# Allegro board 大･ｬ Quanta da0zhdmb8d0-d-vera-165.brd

Outline 236.75 x 98.9 mm; copper layers: TOP, SGND, IN1, SGND1, SVCC, IN2, SGND2, BOTTOM. Coordinates in mm from the lower left corner of the outline.

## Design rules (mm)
net group EDP_TX_DN*: nets EDP_TX_DN*<0> EDP_TX_DN*<1>
net group EDP_TX_DP: nets EDP_TX_DP<0> EDP_TX_DP<1>
net group M_A_CLK_DDR_DN*: nets M_A_CLK_DDR_DN*<0> M_A_CLK_DDR_DN*<1>
net group M_A_CLK_DDR_DP: nets M_A_CLK_DDR_DP<0> M_A_CLK_DDR_DP<1>
net group M_A_CS*: nets M_A_CS*<0> M_A_CS*<1>
net group M_B_CLK_DDR_DN*: nets M_B_CLK_DDR_DN*<0> M_B_CLK_DDR_DN*<1>
net group M_B_CLK_DDR_DP: nets M_B_CLK_DDR_DP<0> M_B_CLK_DDR_DP<1>
net group M_B_CS*: nets M_B_CS*<0> M_B_CS*<1>
net group TP_M_A_A: nets TP_M_A_A<3> TP_M_A_A<4>
net group TP_M_B_A: nets TP_M_B_A<3> TP_M_B_A<4>
net group USBC1_R_SSRXN*: nets USBC1_R_SSRXN*<1> USBC1_R_SSRXN*<2>
net group USBC1_R_SSRXP: nets USBC1_R_SSRXP<1> USBC1_R_SSRXP<2>
net group USBC1_SSRXP: nets USBC1_SSRXP<1> USBC1_SSRXP<2>
net group USBC1_SSTXN*: nets USBC1_SSTXN*<1> USBC1_SSTXN*<2>
net group USBC1_SSTXP: nets USBC1_SSTXP<1> USBC1_SSTXP<2>
net group W12-T12B: nets USB_C0_CC1_CONN USB_C0_CC2_CONN
net group W40-T12B: nets HP_RING2 MIC_P
net group XDP_BPM: nets XDP_BPM<2> XDP_BPM<3>
net group CFG: nets CFG<0> CFG<2> CFG<3> CFG<4> CFG<5> CFG<6> CFG<8> CFG<9> CFG<10>
net group DDI1_LANE_DN*: nets DDI1_LANE_DN*<0> DDI1_LANE_DN*<1> DDI1_LANE_DN*<2> DDI1_LANE_DN*<3>
net group DDI1_LANE_DP: nets DDI1_LANE_DP<0> DDI1_LANE_DP<1> DDI1_LANE_DP<2> DDI1_LANE_DP<3>
net group DDI2_LANE_DN*: nets DDI2_LANE_DN*<0> DDI2_LANE_DN*<1> DDI2_LANE_DN*<2> DDI2_LANE_DN*<3>
net group DDI2_LANE_DP: nets DDI2_LANE_DP<0> DDI2_LANE_DP<1> DDI2_LANE_DP<2> DDI2_LANE_DP<3>
net group DFP-S4.3(4.2)W4.01(3.11)-T12B: nets DDI1_AUX_DN* DDI1_AUX_DP DDI1_C_AUX_DN DDI1_C_AUX_DP DDI2_CTRL_CLK DDI2_CTRL_DATA EDP_AUX_DN* EDP_AUX_DP EDP_AUXN_C_DN EDP_AUXP_C_DP EDP_TXN0_C_DN EDP_TXN1_C_DN EDP_TXP0_C_DP EDP_TXP1_C_DP HDMI_DDCCLK_MB HDMI_DDCDATA_MB INT_HDMICLK+_IC INT_HDMICLK-_IC INT_HDMITX0N_IC INT_HDMITX0P_IC INT_HDMITX1N_IC INT_HDMITX1P_IC INT_HDMITX2N_IC INT_HDMITX2P_IC USB1_BC_DN USB1_BC_DP USB2_1_DN* USB2_1_DP USB2_A_DN* USB2_A_DN_CONN* USB2_A_DP USB2_A_DP_CONN USB3_A_TX_DN* USB3_A_TX_DP USBC1_DN* USBC1_DP USBC1_SSUSBC1_AUX_RFU1 USBC1_SSUSBC1_AUX_RFU1_C USBC1_SSUSBC1_AUX_RFU2 USBC1_SSUSBC1_AUX_RFU2_C WIFI_PCIE_CLK_DN WIFI_PCIE_CLK_DP
net group DFP-S10(9)W4(3)-T12B: nets INT_HDMICLK+_LS INT_HDMICLK-_LS INT_HDMITX0N_LS INT_HDMITX0P_LS INT_HDMITX1N_LS INT_HDMITX1P_LS INT_HDMITX2N_LS INT_HDMITX2P_LS
net group DFP-S10(9)W4.01(3.11)-T12B: nets INT_HDMICLK+_C INT_HDMICLK-_C INT_HDMITX0N_C INT_HDMITX0P_C INT_HDMITX1N_C INT_HDMITX1P_C INT_HDMITX2N_C INT_HDMITX2P_C
net group DFP-S10W4(3)-T1B: nets I2C4_SCL I2C4_SCL_C I2C4_SDA I2C4_SDA_C
net group DFP-S10W4(3.1)-T12B: nets EC_MUX_CLK EC_MUX_SDA EC_PD_I2C_CLK EC_PD_I2C_SDA EC_ROP_I2C_CLK EC_ROP_I2C_SDA EC_SMB_CLK EC_SMB_SDA I2C1_SCL I2C1_SDA I2C_SCL_INA I2C_SDA_INA
net group DFP-S10W12-T12B: nets VCCCORE_SENSE VCCGT_SENSE VCCSA_SENSE VSSCORE_SENSE VSSGT_SENSE VSSSA_SENSE
net group EMMC_D: nets EMMC_D<0> EMMC_D<1> EMMC_D<2> EMMC_D<3> EMMC_D<4> EMMC_D<5> EMMC_D<6> EMMC_D<7>
net group LPC_LAD: nets LPC_LAD<0> LPC_LAD<1> LPC_LAD<2> LPC_LAD<3>
net group M_A_CA_A: nets M_A_CA_A<0> M_A_CA_A<1> M_A_CA_A<2> M_A_CA_A<3> M_A_CA_A<4> M_A_CA_A<5> M_A_CA_A<6> M_A_CA_A<7> M_A_CA_A<8> M_A_CA_A<9>
net group M_A_CA_B: nets M_A_CA_B<0> M_A_CA_B<1> M_A_CA_B<2> M_A_CA_B<3> M_A_CA_B<4> M_A_CA_B<5> M_A_CA_B<6> M_A_CA_B<7> M_A_CA_B<8> M_A_CA_B<9>
net group M_A_CKE: nets M_A_CKE<0> M_A_CKE<1> M_A_CKE<2> M_A_CKE<3>
net group M_A_DQ: nets M_A_DQ<0> M_A_DQ<1> M_A_DQ<2> M_A_DQ<3> M_A_DQ<4> M_A_DQ<5> M_A_DQ<6> M_A_DQ<7> M_A_DQ<8> M_A_DQ<9> M_A_DQ<10> M_A_DQ<11> M_A_DQ<12> M_A_DQ<13> M_A_DQ<14> M_A_DQ<15> M_A_DQ<16> M_A_DQ<17> M_A_DQ<18> M_A_DQ<19> M_A_DQ<20> M_A_DQ<21> M_A_DQ<22> M_A_DQ<23> M_A_DQ<24> M_A_DQ<25> M_A_DQ<26> M_A_DQ<27> M_A_DQ<28> M_A_DQ<29> M_A_DQ<30> M_A_DQ<31> M_A_DQ<32> M_A_DQ<33> M_A_DQ<34> M_A_DQ<35> M_A_DQ<36> M_A_DQ<37> M_A_DQ<38> M_A_DQ<39> M_A_DQ<40> M_A_DQ<41> M_A_DQ<42> M_A_DQ<43> M_A_DQ<44> M_A_DQ<45> M_A_DQ<46> M_A_DQ<47> M_A_DQ<48> M_A_DQ<49> M_A_DQ<50> M_A_DQ<51> M_A_DQ<52> M_A_DQ<53> M_A_DQ<54> M_A_DQ<55> M_A_DQ<56> M_A_DQ<57> M_A_DQ<58> M_A_DQ<59> M_A_DQ<60> M_A_DQ<61> M_A_DQ<62> M_A_DQ<63>
net group M_A_DQS_DN*: nets M_A_DQS_DN*<0> M_A_DQS_DN*<1> M_A_DQS_DN*<2> M_A_DQS_DN*<3> M_A_DQS_DN*<4> M_A_DQS_DN*<5> M_A_DQS_DN*<6> M_A_DQS_DN*<7>
net group M_A_DQS_DP: nets M_A_DQS_DP<0> M_A_DQS_DP<1> M_A_DQS_DP<2> M_A_DQS_DP<3> M_A_DQS_DP<4> M_A_DQS_DP<5> M_A_DQS_DP<6> M_A_DQS_DP<7>
net group M_A_ODT: nets M_A_ODT<0>
net group M_B_CA_A: nets M_B_CA_A<0> M_B_CA_A<1> M_B_CA_A<2> M_B_CA_A<3> M_B_CA_A<4> M_B_CA_A<5> M_B_CA_A<6> M_B_CA_A<7> M_B_CA_A<8> M_B_CA_A<9>
net group M_B_CA_B: nets M_B_CA_B<0> M_B_CA_B<1> M_B_CA_B<2> M_B_CA_B<3> M_B_CA_B<4> M_B_CA_B<5> M_B_CA_B<6> M_B_CA_B<7> M_B_CA_B<8> M_B_CA_B<9>
net group M_B_CKE: nets M_B_CKE<0> M_B_CKE<1> M_B_CKE<2> M_B_CKE<3>
net group M_B_DQ: nets M_B_DQ<0> M_B_DQ<1> M_B_DQ<2> M_B_DQ<3> M_B_DQ<4> M_B_DQ<5> M_B_DQ<6> M_B_DQ<7> M_B_DQ<8> M_B_DQ<9> M_B_DQ<10> M_B_DQ<11> M_B_DQ<12> M_B_DQ<13> M_B_DQ<14> M_B_DQ<15> M_B_DQ<16> M_B_DQ<17> M_B_DQ<18> M_B_DQ<19> M_B_DQ<20> M_B_DQ<21> M_B_DQ<22> M_B_DQ<23> M_B_DQ<24> M_B_DQ<25> M_B_DQ<26> M_B_DQ<27> M_B_DQ<28> M_B_DQ<29> M_B_DQ<30> M_B_DQ<31> M_B_DQ<32> M_B_DQ<33> M_B_DQ<34> M_B_DQ<35> M_B_DQ<36> M_B_DQ<37> M_B_DQ<38> M_B_DQ<39> M_B_DQ<40> M_B_DQ<41> M_B_DQ<42> M_B_DQ<43> M_B_DQ<44> M_B_DQ<45> M_B_DQ<46> M_B_DQ<47> M_B_DQ<48> M_B_DQ<49> M_B_DQ<50> M_B_DQ<51> M_B_DQ<52> M_B_DQ<53> M_B_DQ<54> M_B_DQ<55> M_B_DQ<56> M_B_DQ<57> M_B_DQ<58> M_B_DQ<59> M_B_DQ<60> M_B_DQ<61> M_B_DQ<62> M_B_DQ<63>
net group M_B_DQS_DN*: nets M_B_DQS_DN*<0> M_B_DQS_DN*<1> M_B_DQS_DN*<2> M_B_DQS_DN*<3> M_B_DQS_DN*<4> M_B_DQS_DN*<5> M_B_DQS_DN*<6> M_B_DQS_DN*<7>
net group M_B_DQS_DP: nets M_B_DQS_DP<0> M_B_DQS_DP<1> M_B_DQS_DP<2> M_B_DQS_DP<3> M_B_DQS_DP<4> M_B_DQS_DP<5> M_B_DQS_DP<6> M_B_DQS_DP<7>
net group M_B_ODT: nets M_B_ODT<0>
net group PCIE_RX_DN*: nets PCIE_RX_DN*<1>
net group PCIE_RX_DP: nets PCIE_RX_DP<1>
net group PCIE_TX_C_DN*: nets PCIE_TX_C_DN*<1>
net group PCIE_TX_C_DP: nets PCIE_TX_C_DP<1>
net group PCIE_TX_DN*: nets PCIE_TX_DN*<1>
net group PCIE_TX_DP: nets PCIE_TX_DP<1>
net group USB2_DN*: nets USB2_DN*<1> USB2_DN*<2> USB2_DN*<3> USB2_DN*<5> USB2_DN*<6> USB2_DN*<9>
net group USB2_DP: nets USB2_DP<1> USB2_DP<2> USB2_DP<3> USB2_DP<5> USB2_DP<6> USB2_DP<9>
net group USB2_OC*: nets USB2_OC*<0> USB2_OC*<1> USB2_OC*<2> USB2_OC*<3>
net group USB3_RX_DN*: nets USB3_RX_DN*<1> USB3_RX_DN*<2> USB3_RX_DN*<3> USB3_RX_DN*<4>
net group USB3_RX_DP: nets USB3_RX_DP<1> USB3_RX_DP<2> USB3_RX_DP<3> USB3_RX_DP<4>
net group USB3_TX_DN*: nets USB3_TX_DN*<1> USB3_TX_DN*<2> USB3_TX_DN*<3> USB3_TX_DN*<4> USB3_TX_DN*<4>_C
net group USB3_TX_DP: nets USB3_TX_DP<1> USB3_TX_DP<2> USB3_TX_DP<3> USB3_TX_DP<4> USB3_TX_DP<4>_C
net group USBC1_R_SSTXN*: nets USBC1_R_SSTXN*<1> USBC1_R_SSTXN*<1>_C USBC1_R_SSTXN*<2> USBC1_R_SSTXN*<2>_C
net group USBC1_R_SSTXP: nets USBC1_R_SSTXP<1> USBC1_R_SSTXP<1>_C USBC1_R_SSTXP<2> USBC1_R_SSTXP<2>_C
net group USBC1_SSRXN: nets USBC1_SSRXN<2>
net group USBC1_SSRXN*: nets USBC1_SSRXN*<1>
net group W3.5-T12B: nets EMMC_C2
net group W4(3.1)-T1B: nets CPU_SVIDALRT* CPU_SVIDALRT*_R CPU_SVIDCLK CPU_SVIDDAT IMVP_SVID_CLK IMVP_SVID_DATA
net group W4(3.1)-T12B: nets BUF_PCH_PLT_RST*_R DDI1_CTRL_DATA DDI1_HPD DDI2_HPD DEVICE_PROCHOT* DMIC_CLK0_L DMIC_CLK0_R DMIC_CLK_L2 DMIC_DAT_L2 DMIC_DATA0_L EC_HID_INT* EC_LPC_CLK EC_LPC_CLK_R EC_PCH_PROCHOT EC_RST* EC_SPI_CLK EC_SPI_CS* EC_SPI_MISO EC_SPI_MOSI EC_USBPD_RST* EC_XTAL_IN EC_XTAL_OUT ECRXD_SERVOTXD ECTXD_SERVORXD EDP_HPD EMMC<0> EMMC<1> EMMC<2> EMMC<3> EMMC<4> EMMC<5> EMMC<6> EMMC<7> EMMC_CLK EMMC_CLK_D EMMC_CMD EMMC_CMD_D EMMC_RCLK EMMC_RCLK_D FLASH_SPI_CLK FLASH_SPI_CLK_R FLASH_SPI_CS* FLASH_SPI_MISO FLASH_SPI_MISO_R FLASH_SPI_MISO_TPM FLASH_SPI_MOSI FLASH_SPI_MOSI_R FLASH_SPI_MOSI_TPM I2S0_RXD I2S0_SCLK I2S0_SFRM I2S0_TXD I2S2_RXD I2S2_SCLK I2S2_SFRM I2S2_TXD I2S_MCLK I2S_MCLK_C IMVP8_PROCHOT* ITCH_SPI_CLK ITCH_SPI_CS* ITCH_SPI_IO2 ITCH_SPI_IO3 ITCH_SPI_MISO ITCH_SPI_MOSI LPC_CLKRUN* LPC_FRAME* LPC_SERIRQ MERGE_I2S_PCHRXD_AUDTXD MERGE_I2S_PCHTXD_AUDRXD MERGE_I2S_SCL MERGE_I2S_SFRM N26779690 N29007898 N29008264 N30494257 N34176799 PCH_LPC_CLK1 PCH_PLT_RST* PCH_PWROK PCH_RSMRST* PCH_RSMRST*_R PCH_SUSACK* PCH_SUSPWRACK* PCH_SYSRST* PCH_SYSRST*_R PCHRXD_SERVOTXD PCHTXD_SERVORXD PECI PM_CPUPWRGD ROP_DSW_PWROK ROP_EC_INT* ROP_RESET* ROP_RSMRST_PWRGD* ROP_SYS_PWROK ROP_VCCST_PWRGD RTC_RST* RTC_X1 RTC_X2 SD_CD*_R_R SD_CDZ SERVO_EC_RST* SERVO_EC_SPI_CLK SERVO_EC_SPI_CS* SERVO_EC_SPI_MISO SERVO_EC_SPI_MOSI SERVO_PCH_SPI_CLK SERVO_PCH_SPI_CLK_R SERVO_PCH_SPI_CS* SERVO_PCH_SPI_CS*_R SERVO_PCH_SPI_MISO SERVO_PCH_SPI_MOSI SOC_CATERR* SOC_PROCHOT* SOC_THRMTRIP* SOURCE_EC_PROCHOT* SPI_TPM_IRQ* SRTCRST* SUS_CLK TPM_PLTRST#_R TPM_SPI_CS* TRACKPAD_INT* USB_C0_BC12_INT* USB_C0_CC1_DEVICE_ODL USB_C0_CC1_MCU USB_C0_CC1_TX_DATA USB_C0_CC2_DEVICE_ODL USB_C0_CC2_MCU USB_C0_CC2_TX_DATA USB_C0_HOST_HIGH USB_C0_TX_CLKIN USB_C0_TX_CLKOUT USBPDRXD_SERVOTXD USBPDTXD_SERVORXD VCCST_PWRGD_MCP WIFI_CLK_REQ* XCLK_BIASREF XTAL24_IN XTAL24_IN_R XTAL24_OUT XTAL24_OUT_R
net group W5-T12B: nets +VCCCORE +VCCGT +VCCSA +VDDQ_MEM EDP_COMP VDCSNS VREF1.25V
net group W6-T12B: nets +V3P3A_EC +V3P3A_WIFI +VBATA_C +VCCPGPPB LCD_VCC LCD_VCC_OUT SM_RCOMP_0 SM_RCOMP_1 SM_RCOMP_2
net group W7-T12B: nets +V_BOOSTIN +VBATA +VBATT
net group W8-T12B: nets +USB3_P4_VBUS +V3P3_BIOS_SPI_SERVO +V3P3_TP +V3P3_TP_OUT +V3P3A +V3P3A_DSW +V3P3A_EC_ANA +V3P3A_EC_SPI +V3P3A_EC_SPI_SERVO +V3P3A_RTC +V3P3A_TPM +V3P3DSW_EC +VCCDUSB_1P0 +VCCFHV +VUSBC1_VBUS_CONN CPU_POPIRCOMP CSI2_COMP EDRAM_OPIO_RCOMP EMMC_RCOMP EOPIO_RCOMP MA_A_ZQ0 MA_A_ZQ1 MA_B_ZQ0 MA_B_ZQ1 MB_A_ZQ0 MB_A_ZQ1 MB_B_ZQ0 MB_B_ZQ1 N26719512 N26719514 N26719516 PCH_POPIRCOMP RCOMP SD_RCOMP TPM_PP U86_6 VCCRTCEXT
net group W10-T12B: nets +V1P00S_VCCST +V1P00S_VCCSTG +V1P8S_EMMC +V3_LDO +V3P3_BIOS_SPI +V3P3_USBPD +V3P3S +V5_LDO +V5_LDO_T9 +V5_LDO_T10 +V5A +VCC19P2_1P0 +VCC24TBT_1P0 +VCCAMPHYPLL_1P0 +VCCAPLL_1P0 +VCCAPLLEBB_1P0 +VCCATS +VCCDSW_1P0 +VCCDTS_1P0 +VCCF24NS_1P0 +VCCF100_1P0 +VCCF100OC_1P0 +VCCF135_1P0 +VCCMPHYAON_1P0 +VCCMPHYGTAON_1P0 +VCCPAZIO +VCCPDSW_3P3 +VCCPGPPA +VCCPGPPC +VCCPGPPD +VCCPGPPE +VCCPGPPF +VCCPGPPG +VCCPRIM_1P0 +VCCPRIM_3P3 +VCCPRIM_CORE +VCCPRTC_3P3 +VCCPRTCPRIM_3P3 +VCCPSPI +VCCSRAM_1P0 +VR3_VBATA +VR5_VBATA EMMC_3P3 USB_C_REF
net group W15-T12B: nets +V1P8A +V1P8S +V1P8U +V5S_FAN CA_VREF DDR_CA_VREF DDR_VREFDQ_CHA DDR_VREFDQ_CHB PCIE_RCOMPN PCIE_RCOMPP USB2_COMP VREFDQ_CHA VREFDQ_CHB
net group W20-T12B: nets +V1P00A +V1P8S_R951 +V3P3A_R950 +V3P3DX_EDP_FUSE +V3P3S_R955 +VR1_VBATA +VR4_VBATA AUDIO_JACK_JD CAP1_GND CAP2_GND CAP3_GND CAP5_GND HP_CN_OUT_L HP_CN_OUT_R HP_OUT_L HP_OUT_R HP_SLEEVE MIC_N
net group W30-T12B: nets SPK_OUT_L_N SPK_OUT_L_P SPK_OUT_R_N SPK_OUT_R_P

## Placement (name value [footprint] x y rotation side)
C1  *0.01U/50V_4  [C0402]  34.13 55.41 270 top
C1C4  2.2uF/10V_4  [C0402]  20.29 21.5 270 top
C1C7  10u/10V_4  [C0402_2]  90.58 56.41 90 bottom
C1C28  10u/10V_4  [C0402_2]  27.53 24.67 180 top
C1C29  10u/10V_4  [C0402_2]  27.53 23.27 180 top
C1C41  2.2uF/10V_4  [C0402]  21.13 10.02 90 top
C1C42  2.2uF/10V_4  [C0402]  27.78 14.77 270 top
C1C43  2.2uF/10V_4  [C0402]  28.16 11.51 180 top
C1C44  4.7uF/10V_4  [C0402_2]  25.11 10.02 270 top
C1C45  2.2uF/10V_4  [C0402]  27.78 12.99 90 top
C1C47  4.7uF/10V_4  [C0402_2]  18.13 7.27 270 top
C1C48  4.7uF/10V_4  [C0402_2]  17.87 15.02 90 top
C1C50  *0.1U/16V_4  [C0402]  18 21.5 270 top
C1D8  10u/10V_4  [C0402_2]  32.99 27.47 180 top
C1D17  10u/10V_4  [C0402_2]  29.56 13.37 90 top
C1M4  0.1U/16V_4  [C0402]  26.36 10.17 90 top
C1M5  0.1U/16V_4  [C0402]  23.33 9.94 90 top
C1M6  0.1U/16V_4  [C0402]  21.3 20.73 270 top
C1M7  1000p/50V_4  [C0402]  16.86 17.18 90 top
C1M8  0.1U/16V_4  [C0402]  22.45 20.73 270 top
C1M9  0.1U/16V_4  [C0402]  19.78 10.78 0 top
C1P4  *680pF_4  [C0402]  36.4 13.16 90 top
C1P5  *680pF_4  [C0402]  37.41 13.16 90 top
C1P6  *680pF_4  [C0402]  33.62 14 0 top
C1P7  *680pF_4  [C0402]  31.34 13.62 270 top
C2  0.1U/16V_4  [C0402]  93.78 55.09 270 bottom
C2B3  1U/6.3V_4  [C0402]  203.04 19.97 270 top
C2M1  10u/10V_4  [C0402_2]  29.81 18.19 180 top
C2M2  10u/10V_4  [C0402_2]  34.76 16.29 0 top
C2M3  10u/10V_4  [C0402_2]  27.63 10.17 90 top
C2M4  10u/10V_4  [C0402_2]  22.22 9.94 90 top
C2M5  10u/10V_4  [C0402_2]  19.65 19.85 0 top
C3  *470p/50V_4  [C0402]  15.97 11.46 90 top
C4  *470p/50V_4  [C0402]  17.75 9.3 90 top
C7L11  0.1U/16V_4  [C0402]  37.05 55.66 90 bottom
C7L12  0.1U/16V_4  [C0402]  38.19 55.66 90 bottom
C7L13  0.1U/16V_4  [C0402]  38.57 57.44 90 bottom
C7L14  0.1U/16V_4  [C0402]  39.72 57.44 90 bottom
C7L15  0.1U/16V_4  [C0402]  40.1 55.66 90 bottom
C8L3  0.1U/16V_4  [C0402]  42 57.77 180 bottom
C8L6  0.1U/16V_4  [C0402]  41.24 55.66 90 bottom
C8L7  0.1u/25V_4  [C0402]  35.15 58.07 180 bottom
C8L9  1000p/50V_4  [C0402]  35.15 56.93 180 bottom
C8L11  22u/25V_8  [C0805]  32.48 57.44 0 bottom
C8L13  1000p/50V_4  [C0402]  28.06 62.47 0 top
C8L14  0.1u/25V_4  [C0402]  28.43 64.25 270 top
C8L15  1000p/50V_4  [C0402]  51.02 33.26 90 bottom
C8L16  0.1u/25V_4  [C0402]  52.11 33.26 90 bottom
C8L17  1000p/50V_4  [C0402]  25.78 67.66 0 bottom
C8L18  0.1u/25V_4  [C0402]  31.2 68.67 180 bottom
C8L19  1000p/50V_4  [C0402]  31.22 67.67 180 bottom
C8L20  0.1u/25V_4  [C0402]  17.63 69.73 0 top
C32  0.01U/50V_4  [C0402]  195.01 20.99 0 top
C35  10u/10V_4  [C0402_2]  195.01 22.13 0 top
C43  0.1U/16V_4  [C0402]  195.01 19.97 180 top
C51  22u/6.3V_6  [C0603]  136.24 59.98 180 top
C62  22u/6.3V_6  [C0603]  131.67 53.75 90 top
C63  22u/6.3V_6  [C0603]  130.14 53.75 90 top
C64  22u/6.3V_6  [C0603]  137.1 56.98 90 top
C65  22u/6.3V_6  [C0603]  136.24 53.75 90 top
C67  *10p/50V_4  [C0402]  51.53 56.68 0 bottom
C72  0.01U/50V_4  [C0402]  44.67 56.17 270 bottom
C129  0.1U/16V_4  [C0402]  24.66 41.28 0 top
C130  *220p/50V_4  [C0402]  183.86 66.96 180 bottom
C131  10u/10V_4  [C0402_2]  185.89 66.96 0 bottom
C132  0.1U/16V_4  [C0402]  185.89 68.11 180 bottom
C133  10u/10V_4  [C0402_2]  41.22 53.3 270 top
C135  0.01U/50V_4  [C0402]  44.04 58.96 270 top
C136  0.1U/16V_4  [C0402]  45.18 58.96 270 top
C137  10u/10V_4  [C0402_2]  46.45 58.96 270 top
C139  0.1U/16V_4  [C0402]  24.66 43.64 0 top
C141  0.1U/16V_4  [C0402]  24.66 44.66 0 top
C151  0.1U/16V_4  [C0402]  24.66 46.87 0 top
C153  *220p/50V_4  [C0402]  18.66 51.54 90 bottom
C186  33P/50V_4  [C0402]  124.88 37.63 0 bottom
C187  33P/50V_4  [C0402]  122.62 37.63 180 bottom
C289  15P/50V_4  [C0402]  106.52 76.72 180 bottom
C291  15P/50V_4  [C0402]  104.74 76.72 0 bottom
C340  0.1U/16V_4  [C0402]  23.69 48.19 0 top
C341  0.1U/16V_4  [C0402]  23.69 49.31 0 top
C343  0.1U/16V_4  [C0402]  19.91 39.86 180 top
C344  0.1U/16V_4  [C0402]  19.91 38.74 180 top
C386  0.1U/16V_4  [C0402]  18.51 29.62 270 top
C437  1U/6.3V_4  [C0402]  178.53 85.25 0 top
C590  0.1U/16V_4  [C0402]  152.62 23.4 90 top
C783  180P/50V_4  [C0402]  45.81 58.07 270 bottom
C785  180P/50V_4  [C0402]  163.03 22.51 90 bottom
C789  0.01U/50V_4  [C0402]  194.78 11.46 0 top
C790  10u/10V_4  [C0402_2]  194.78 13.88 0 top
C791  0.1U/16V_4  [C0402]  194.78 12.61 180 top
C827  0.1U/16V_4  [C0402]  115.16 39.66 270 bottom
C828  0.1U/16V_4  [C0402]  116.12 39.66 270 bottom
C831  22p/50V_4  [C0402]  78.07 49.56 0 top
C832  18P/50V_4  [C0402]  79.85 49.56 180 top
C842  470p/50V_4  [C0402]  175.35 26.83 90 top
C843  2200P/50V_4  [C0402]  176.12 20.23 270 top
C849  0.1U/16V_4  [C0402]  24.6 71.03 90 top
C850  0.1U/16V_4  [C0402]  25.62 67.98 270 top
C867  0.1U/16V_4  [C0402]  36.92 55.53 90 top
C868  4.7uF/10V_4  [C0402_2]  39.72 53.12 0 top
C870  0.1U/16V_4  [C0402]  23.21 64.04 180 top
C871  0.1U/16V_4  [C0402]  20.67 64.04 0 top
C872  0.1U/16V_4  [C0402]  20.67 61.63 0 top
C873  0.1U/16V_4  [C0402]  23.21 62.14 180 top
C887  1800P/50V_4  [C0402]  28.47 54.77 180 top
C888  1800P/50V_4  [C0402]  28.41 51.72 180 top
C893  0.1U/16V_4  [C0402]  28.41 46.52 180 top
C946  270p/50V_4  [C0402]  30.83 56.29 0 top
C947  270p/50V_4  [C0402]  17.16 55.74 180 bottom
C948  270p/50V_4  [C0402]  15.28 57.21 270 top
C952  *220p/50V_4  [C0402]  181.96 66.96 0 bottom
C968  270p/50V_4  [C0402]  74.9 38.64 90 bottom
C981  0.1U/16V_4  [C0402]  27.37 44.46 0 top
C982  0.1U/16V_4  [C0402]  27.37 45.47 0 top
C983  0.1U/16V_4  [C0402]  24.66 45.85 0 top
C984  0.1U/16V_4  [C0402]  24.66 42.32 0 top
C1009  4.7uF/10V_4  [C0402_2]  20.67 56.55 180 top
C1024  0.1U/16V_4  [C0402]  86.71 23.27 180 bottom
C1025  *1000p/50V_4  [C0402]  88.1 25.31 180 bottom
C1026  1000p/50V_4  [C0402]  88.1 24.29 180 bottom
C1027  0.01U/50V_4  [C0402]  80.36 31.78 270 bottom
C1028  0.1U/16V_4  [C0402]  79.21 31.78 270 bottom
C1029  22u/6.3V_6  [C0603]  133.19 53.75 90 top
C1030  22u/6.3V_6  [C0603]  131.28 61.68 180 top
C1031  22u/6.3V_6  [C0603]  134.05 59.62 90 top
C1032  22u/6.3V_6  [C0603]  129.25 59.72 90 top
C1033  22u/6.3V_6  [C0603]  133.95 61.68 0 top
C1080  10u/10V_4  [C0402_2]  32.73 56.17 0 top
C1087  22u/6.3V_6  [C0603]  105.5 36.74 180 bottom
C1088  22u/6.3V_6  [C0603]  105.5 35.21 180 bottom
C1089  *0.22u/10V_4  [C0402]  77.39 44.86 90 top
C1102  22u/6.3V_6  [C0603]  113.01 50.21 270 top
C1103  22u/6.3V_6  [C0603]  96.66 52.76 0 top
C1104  0.1U/16V_4  [C0402]  15.84 47.28 180 bottom
C1105  180P/50V_4  [C0402]  194.78 15.4 180 top
C1106  180P/50V_4  [C0402]  178.14 90.11 0 top
C1107  *22p/50V_4  [C0402]  35.53 23.91 270 top
C1109  0.1U/16V_4  [C0402]  96.43 77.24 180 bottom
C1110  *10p/50V_4  [C0402]  53.56 56.68 180 bottom
C1111  100p/50V_4  [C0402]  26.96 69.27 270 bottom
C1112  100p/50V_4  [C0402]  25.73 69.21 270 bottom
C1113  33P/50V_4  [C0402]  25.11 20.35 0 top
C1114  33P/50V_4  [C0402]  27.14 20.35 180 top
C1115  *4.7uF/10V_4  [C0402_2]  20.67 59.09 180 top
C1116  1000p/50V_4  [C0402]  74.13 36.61 270 bottom
C1136  *3.3P/50V_4  [C0402]  70.32 53.68 180 bottom
C1137  *3.3P/50V_4  [C0402]  70.32 44.36 180 bottom
C1138  33P/50V_4  [C0402]  110.98 37.82 270 top
C1139  33P/50V_4  [C0402]  112.25 37.82 270 top
C1140  10u/10V_4  [C0402_2]  115.78 52.61 90 top
C1141  10u/10V_4  [C0402_2]  113.5 40.04 180 top
C1142  0.1U/16V_4  [C0402]  36.8 57.69 270 bottom
C6001  *0.1U/16V_4  [C0402]  101.98 38.68 270 top
C6002  *0.1U/16V_4  [C0402]  96.65 79.57 90 bottom
C6003  *0.1U/16V_4  [C0402]  87.09 81.44 180 top
C6004  *0.1U/16V_4  [C0402]  93.44 88.93 180 bottom
C6005  *0.1U/16V_4  [C0402]  145.27 39.01 270 bottom
CAP1020  22nF/16V_4  [C0402]  171.67 83.22 180 top
CAP1022  22nF/16V_4  [C0402]  166.34 83.23 180 top
CAP1024  22nF/16V_4  [C0402]  168.97 83.26 180 top
CAP1073  1U/6.3V_4  [C0402]  100.42 77.88 180 bottom
CAP1079  1U/6.3V_4  [C0402]  100.3 78.9 180 bottom
CAP1101  *10u/6.3V_4  [C0402_2]  158.34 59.09 270 top
CAP1102  1U/6.3V_2  [C0201]  128.92 55.33 0 top
CAP1103  1U/6.3V_2  [C0201]  139.39 57.06 270 top
CAP1108  *10u/6.3V_4  [C0402_2]  159.61 59.09 270 top
CAP1109  1U/6.3V_2  [C0201]  140.48 56.8 270 top
CAP1110  1U/6.3V_2  [C0201]  144.06 51.01 0 top
CAP1115  *10u/6.3V_4  [C0402_2]  160.88 59.09 270 top
CAP1116  1U/6.3V_2  [C0201]  140.45 53.3 0 top
CAP1117  1U/6.3V_2  [C0201]  128.97 51.72 0 top
CAP1122  *10u/6.3V_4  [C0402_2]  132.43 50.66 90 top
CAP1123  1U/6.3V_2  [C0201]  128.49 52.48 0 top
CAP1124  1U/6.3V_2  [C0201]  141.13 52.15 90 top
CAP1129  *10u/6.3V_4  [C0402_2]  157.07 57.18 90 top
CAP1130  1U/6.3V_2  [C0201]  137.76 50.25 90 top
CAP1131  1U/6.3V_2  [C0201]  142.08 50.96 90 top
CAP1136  *10u/6.3V_4  [C0402_2]  153.26 57.16 90 top
CAP1137  1U/6.3V_2  [C0201]  138.52 54.26 0 top
CAP1138  1U/6.3V_2  [C0201]  130.7 50.25 90 top
CAP1141  *10u/6.3V_4  [C0402_2]  138.63 55.48 90 top
CAP1142  1U/6.3V_2  [C0201]  134.41 50.3 90 top
CAP1147  *10u/6.3V_4  [C0402_2]  162.15 59.09 270 top
CAP1148  1U/6.3V_2  [C0201]  140.56 55.02 270 top
CAP1150  *10u/6.3V_4  [C0402_2]  157.07 59.09 270 top
CAP1152  *10u/6.3V_4  [C0402_2]  142.46 40.29 90 top
CAP1155  22u/6.3V_6  [C0603]  129.25 57.08 90 top
CAP1156  10u/6.3V_4  [C0402_2]  142.46 56.04 270 top
CAP1157  10u/6.3V_4  [C0402_2]  138.42 57.34 270 top
CAP1159  22u/6.3V_6  [C0603]  132.38 56.95 90 top
CAP1161  22u/6.3V_6  [C0603]  130.8 56.95 90 top
CAP1162  10u/6.3V_4  [C0402_2]  137.61 51.57 180 top
CAP1164  22u/6.3V_6  [C0603]  135.58 56.98 90 top
CAP1165  10u/6.3V_4  [C0402_2]  142.46 54.26 270 top
CAP1166  22u/6.3V_6  [C0603]  133.93 56.98 90 top
CAP1167  10u/6.3V_4  [C0402_2]  143.27 59.72 270 top
CAP1168  22u/6.3V_6  [C0603]  130.8 59.62 90 top
CAP1169  10u/6.3V_4  [C0402_2]  142.89 49.69 0 top
CAP1171  22u/6.3V_6  [C0603]  132.94 28.23 270 bottom
CAP1172  22u/6.3V_6  [C0603]  128.36 28.23 270 bottom
CAP1173  22u/6.3V_6  [C0603]  124.55 31.81 180 bottom
CAP1174  10u/6.3V_4  [C0402_2]  124.71 54.16 270 top
CAP1176  1U/6.3V_2  [C0201]  126.56 59.44 180 top
CAP1177  1U/6.3V_2  [C0201]  125.62 59.6 90 top
CAP1178  22u/6.3V_6  [C0603]  134.71 53.75 90 top
CAP1179  10u/6.3V_4  [C0402_2]  153.26 59.09 270 top
CAP1181  22u/6.3V_6  [C0603]  134.46 28.23 270 bottom
CAP1183  22u/6.3V_6  [C0603]  124.65 33.25 180 bottom
CAP1184  10u/6.3V_4  [C0402_2]  127.55 58.49 180 top
CAP1186  1U/6.3V_2  [C0201]  126.58 60.18 180 top
CAP1187  1U/6.3V_2  [C0201]  124.5 58.63 180 top
CAP1189  10u/6.3V_4  [C0402_2]  136.24 61.5 0 top
CAP1191  22u/6.3V_6  [C0603]  119.96 41.69 270 bottom
CAP1192  22u/6.3V_6  [C0603]  121.46 38.06 180 top
CAP1193  22u/6.3V_6  [C0603]  126.61 36.2 90 bottom
CAP1194  10u/6.3V_4  [C0402_2]  122.27 50.2 0 top
CAP1196  1U/6.3V_2  [C0201]  124.88 59.62 90 top
CAP1197  1U/6.3V_2  [C0201]  121.2 57.31 0 top
CAP1199  10u/6.3V_4  [C0402_2]  155.8 55.28 270 top
CAP1201  22u/6.3V_6  [C0603]  128.14 36.2 90 bottom
CAP1203  22u/6.3V_6  [C0603]  129.89 28.23 270 bottom
CAP1204  10u/6.3V_4  [C0402_2]  121.35 54.11 0 top
CAP1206  1U/6.3V_2  [C0201]  121.2 58.07 0 top
CAP1207  1U/6.3V_2  [C0201]  121.25 59.6 0 top
CAP1208  22u/6.3V_6  [C0603]  121.45 39.54 180 top
CAP1210  22u/6.3V_6  [C0603]  124.55 30.39 180 bottom
CAP1211  10u/6.3V_4  [C0402_2]  123.08 56.9 0 top
CAP1213  1U/6.3V_2  [C0201]  136.62 37.88 270 bottom
CAP1214  1U/6.3V_2  [C0201]  122.37 51.47 0 top
CAP1215  22u/6.3V_6  [C0603]  123.17 59.72 180 top
CAP1217  22u/6.3V_6  [C0603]  126.84 28.23 270 bottom
CAP1218  10u/6.3V_4  [C0402_2]  127.55 56.09 180 top
CAP1220  1U/6.3V_2  [C0201]  120.87 50.2 0 top
CAP1221  1U/6.3V_2  [C0201]  126.28 56.9 90 top
CAP1223  22u/6.3V_6  [C0603]  124.55 28.96 180 bottom
CAP1224  10u/6.3V_4  [C0402_2]  124.86 56.9 180 top
CAP1226  1U/6.3V_2  [C0201]  135.72 35.89 270 bottom
CAP1227  1U/6.3V_2  [C0201]  125.65 31.45 0 top
CAP1229  22u/6.3V_6  [C0603]  125.06 39.02 0 top
CAP1231  1U/6.3V_2  [C0201]  125.65 32.16 0 top
CAP1232  1U/6.3V_2  [C0201]  125.65 32.88 0 top
CAP1234  22u/6.3V_6  [C0603]  126.38 54.16 90 top
CAP1235  1U/6.3V_2  [C0201]  125.65 33.64 0 top
CAP1236  1U/6.3V_2  [C0201]  125.65 30.69 0 top
CAP1240  10u/6.3V_4  [C0402_2]  125.06 72.55 180 top
CAP1241  10u/6.3V_4  [C0402_2]  123.16 70.9 0 top
CAP1242  *10u/6.3V_4  [C0402_2]  123.16 73.95 0 top
CAP1243  *1U/6.3V_2  [C0201]  131.16 71.28 270 top
CAP1244  1U/6.3V_4  [C0402]  113.04 52.71 180 top
CAP1245  22u/6.3V_6  [C0603]  105.3 73.24 90 top
CAP1247  10u/6.3V_4  [C0402_2]  126.59 61.48 90 top
CAP1248  *1U/6.3V_2  [C0201]  126.84 71.56 180 top
CAP1249  1U/6.3V_4  [C0402]  113.5 41.31 0 top
CAP1250  1U/6.3V_2  [C0201]  117.52 61.73 180 top
CAP1252  22u/6.3V_6  [C0603]  106.14 71.15 0 top
CAP1253  *10u/6.3V_4  [C0402_2]  129.83 71.78 270 top
CAP1254  *1U/6.3V_2  [C0201]  124.93 71.53 180 top
CAP1255  *47u/10V_8  [C0805]  91.63 52.57 180 bottom
CAP1256  *1u/6.3V_4  [C0402]  115.11 54.17 180 top
CAP1257  10u/6.3V_4  [C0402_2]  123.16 72.55 0 top
CAP1258  *1U/6.3V_2  [C0201]  126.84 70.67 180 top
CAP1259  1U/6.3V_2  [C0201]  124.93 70.77 180 top
CAP1260  1U/6.3V_4  [C0402]  116.32 42.17 90 bottom
CAP1261  1U/6.3V_4  [C0402]  116.86 52.23 270 top
CAP1262  1U/6.3V_4  [C0402]  99.92 51.16 0 bottom
CAP1264  22u/6.3V_6  [C0603]  126.84 74.07 0 top
CAP1265  10u/6.3V_4  [C0402_2]  128.36 71.79 270 top
CAP1267  1U/6.3V_4  [C0402]  99.36 60.78 0 bottom
CAP1268  *1u/6.3V_4  [C0402]  113.89 71.53 0 top
CAP1270  22u/6.3V_6  [C0603]  132.43 71.92 90 top
CAP1271  1U/6.3V_4  [C0402]  107.03 41.31 180 top
CAP1272  *1u/6.3V_4  [C0402]  116.55 56.32 270 top
CAP1274  22u/6.3V_6  [C0603]  126.84 75.6 0 top
CAP1275  *1u/6.3V_4  [C0402]  115.54 71.53 270 top
CAP1276  *1u/6.3V_4  [C0402]  97.15 58.68 90 top
CAP1277  1U/6.3V_2  [C0201]  127.73 61.63 90 top
CAP1278  1U/6.3V_2  [C0201]  119.78 61.29 0 top
CAP1279  *1u/6.3V_4  [C0402]  93.05 74.42 0 bottom
CAP1280  1U/6.3V_2  [C0201]  120.74 60.31 180 top
CAP1281  10u/6.3V_4  [C0402_2]  117.95 59.34 0 top
CAP1282  0.1U/16V_4  [C0402]  109.57 72.04 90 top
CAP1283  1U/6.3V_2  [C0201]  121.84 62.49 270 top
CAP1284  10u/6.3V_4  [C0402_2]  118.97 38.31 180 top
CAP1285  10u/6.3V_4  [C0402_2]  119.73 54.21 270 top
CAP1286  1U/6.3V_2  [C0201]  120.24 49.31 180 top
CAP1287  *1u/6.3V_4  [C0402]  92.39 54.05 180 bottom
CAP1288  *1U/6.3V_2  [C0201]  119.79 62 0 top
CAP1289  10u/6.3V_4  [C0402_2]  118.97 40.9 180 top
CAP1290  10u/6.3V_4  [C0402_2]  116.88 50.4 0 top
CAP1291  1U/6.3V_2  [C0201]  115.92 49.26 0 top
CAP1292  *1U/6.3V_2  [C0201]  121.66 61.48 90 top
CAP1293  10u/6.3V_4  [C0402_2]  117.95 58.07 0 top
CAP1294  10u/6.3V_4  [C0402_2]  117.95 55.53 0 top
CAP1295  1U/6.3V_2  [C0201]  116.59 60.15 270 top
CAP1296  *1u/6.3V_4  [C0402]  94.42 57.71 180 bottom
CAP1297  *1u/6.3V_4  [C0402]  106.65 41.94 0 bottom
CAP1298  *1U/6.3V_2  [C0201]  120.9 61.48 90 top
CAP1299  10u/6.3V_4  [C0402_2]  117.95 56.8 0 top
CAP1300  10u/6.3V_4  [C0402_2]  118.2 53.25 180 top
CAP1301  1U/6.3V_2  [C0201]  119.68 57.31 180 top
CAP1302  *1U/6.3V_2  [C0201]  119.73 60.23 0 top
CAP1303  10u/6.3V_4  [C0402_2]  118.97 39.58 180 top
CAP1304  10u/6.3V_4  [C0402_2]  119.63 58.94 270 top
CAP1305  1U/6.3V_2  [C0201]  119.85 50.2 180 top
CAP1306  *47u/10V_8  [C0805]  108.68 34.45 90 bottom
CAP1307  *10u/6.3V_4  [C0402_2]  117.4 42.17 90 bottom
CAP1308  22u/6.3V_6  [C0603]  118.71 39.15 0 bottom
CAP1309  10u/6.3V_4  [C0402_2]  119.98 52.48 180 top
CAP1310  1U/6.3V_2  [C0201]  118.56 50.25 270 top
CAP1311  1U/6.3V_4  [C0402]  99.95 56.93 0 bottom
CAP1312  *47u/10V_8  [C0805]  102.05 34.53 180 bottom
CAP1313  *10u/6.3V_4  [C0402_2]  118.62 42.2 90 bottom
CAP1316  1U/6.3V_2  [C0201]  118.31 60.82 270 top
CAP1317  1U/6.3V_4  [C0402]  101.35 72.21 180 top
CAP1318  1U/6.3V_4  [C0402]  111.73 71.28 270 top
CAP1319  0.1U/16V_4  [C0402]  101.91 73.18 0 top
CAP1320  0.1U/16V_4  [C0402]  101.35 71.18 0 top
CAP1321  *47u/10V_8  [C0805]  98.82 34.53 180 bottom
CAP1422  0.1u/10V_2  [C0201]  73.37 59.6 0 bottom
CAP1423  0.1u/10V_2  [C0201]  71.85 59.34 270 bottom
CAP1424  1U/6.3V_2  [C0201]  127.65 59.43 180 top
CAP1425  1U/6.3V_2  [C0201]  125.29 52.41 270 top
CAP1426  1U/6.3V_2  [C0201]  126.23 52.36 270 top
CAP1427  1U/6.3V_2  [C0201]  124.16 51.59 0 top
CAP1428  1U/6.3V_2  [C0201]  127.65 60.14 180 top
CAP1429  1U/6.3V_2  [C0201]  121.2 56.55 0 top
CAP1430  1U/6.3V_2  [C0201]  122.88 58.02 90 top
CAP1431  1U/6.3V_2  [C0201]  122.55 62.49 270 top
CAP1432  1U/6.3V_2  [C0201]  121.2 58.83 0 top
CAP1433  1U/6.3V_2  [C0201]  127.6 54.01 180 top
CAP1434  1U/6.3V_2  [C0201]  125.98 51.49 0 top
CAP1435  1U/6.3V_2  [C0201]  127.6 53.25 180 top
CAP1436  1U/6.3V_2  [C0201]  127.6 54.77 180 top
CAP1437  1U/6.3V_2  [C0201]  127.4 51.72 180 top
CAP1438  1U/6.3V_2  [C0201]  127.45 52.48 180 top
CAP1439  1U/6.3V_2  [C0201]  125.87 58.12 90 top
CAP1441  1U/6.3V_2  [C0201]  124.27 52.46 270 top
CAP1442  10u/6.3V_4  [C0402_2]  122.47 52.53 0 top
CAP1443  10u/6.3V_4  [C0402_2]  121.35 55.53 0 top
CAP1444  10u/6.3V_4  [C0402_2]  127.55 57.3 180 top
CAP1445  10u/6.3V_4  [C0402_2]  122.52 42.2 90 bottom
CAP1446  10u/6.3V_4  [C0402_2]  125.6 42.48 180 bottom
CAP1447  10u/6.3V_4  [C0402_2]  121.33 42.2 90 bottom
CAP1448  10u/6.3V_4  [C0402_2]  131.46 41.05 180 top
CAP1449  10u/6.3V_4  [C0402_2]  131.46 39.78 180 top
CAP1450  10u/6.3V_4  [C0402_2]  135.67 50.31 180 top
CAP1451  10u/6.3V_4  [C0402_2]  154.53 57.18 90 top
CAP1452  10u/6.3V_4  [C0402_2]  143.91 52.38 90 top
CAP1456  *10u/6.3V_4  [C0402_2]  142.08 59.72 270 top
CAP1457  *10u/6.3V_4  [C0402_2]  128.82 53.86 270 top
CAP1458  *10u/6.3V_4  [C0402_2]  166.21 56.8 270 bottom
CAP1459  *10u/6.3V_4  [C0402_2]  164.94 56.8 270 bottom
CAP1460  *10u/6.3V_4  [C0402_2]  167.48 56.8 270 bottom
CAP1461  *10u/6.3V_4  [C0402_2]  153.21 55.28 270 top
CAP1462  *10u/6.3V_4  [C0402_2]  170.02 56.8 270 bottom
CAP1463  *10u/6.3V_4  [C0402_2]  168.75 56.8 270 bottom
CAP1464  *10u/6.3V_4  [C0402_2]  162.4 56.8 270 bottom
CAP1465  *10u/6.3V_4  [C0402_2]  171.29 56.8 270 bottom
CAP1467  *10u/6.3V_4  [C0402_2]  161.13 56.8 270 bottom
CAP1468  *10u/6.3V_4  [C0402_2]  138.57 59.6 270 top
CAP1469  *10u/6.3V_4  [C0402_2]  154.53 55.28 270 top
CAP1470  *10u/6.3V_4  [C0402_2]  163.67 56.8 270 bottom
CAP1471  *10u/6.3V_4  [C0402_2]  161.51 55.66 270 top
CAP1472  *10u/6.3V_4  [C0402_2]  155.82 59.09 270 top
CAP1473  *10u/6.3V_4  [C0402_2]  140.35 49.54 180 top
CAP1474  *10u/6.3V_4  [C0402_2]  154.53 59.09 270 top
CAP1475  *10u/6.3V_4  [C0402_2]  129 50.45 90 top
CAP1476  *1U/6.3V_2  [C0201]  133.44 50.3 90 top
CAP1477  *1U/6.3V_2  [C0201]  159.05 57.56 90 top
CAP1478  *1U/6.3V_2  [C0201]  142.53 52.73 0 top
CAP1479  *1U/6.3V_2  [C0201]  141.27 58.07 90 top
CAP1480  *1U/6.3V_2  [C0201]  159.99 56.8 270 bottom
CAP1481  *1U/6.3V_2  [C0201]  158.23 57.57 90 top
CAP1482  *1U/6.3V_2  [C0201]  137.51 54.01 0 top
CAP1483  *1U/6.3V_2  [C0201]  141.98 51.82 0 top
CAP1484  *1U/6.3V_2  [C0201]  137.51 53.25 0 top
CAP1485  *1U/6.3V_2  [C0201]  143.15 58.05 270 top
CAP1486  *1U/6.3V_2  [C0201]  143.21 50.88 270 top
CAP1487  *1U/6.3V_2  [C0201]  129.99 50.25 90 top
CAP1488  *1U/6.3V_2  [C0201]  143.73 55.91 90 top
CAP1489  *1U/6.3V_2  [C0201]  144.24 54.52 270 top
CAP1490  *1U/6.3V_2  [C0201]  131.41 50.25 90 top
CAP1491  *1U/6.3V_2  [C0201]  144.04 58.02 270 top
CAP1492  *1U/6.3V_2  [C0201]  139.24 53.4 90 top
CAP1493  *1U/6.3V_2  [C0201]  144.24 59.75 270 top
CAP1494  *1U/6.3V_2  [C0201]  136.95 50.3 90 top
CAP1495  *1U/6.3V_2  [C0201]  141.33 54.05 270 top
CAP1498  0.1u/10V_2  [C0201]  62.83 58.58 270 top
CAP1499  0.1u/10V_2  [C0201]  60.52 53.7 180 top
CAP1500  1U/6.3V_2  [C0201]  54.58 59.47 0 top
CAP14466  *10u/6.3V_4  [C0402_2]  155.8 57.18 90 top
CAP14472  *0.1u/10V_2  [C0201]  108.68 72.55 90 top
CAP14473  22u/6.3V_6  [C0603]  125.06 40.55 0 top
CAP14474  22u/6.3V_6  [C0603]  124.45 50.3 180 top
CAP14475  22u/6.3V_6  [C0603]  127.09 50.35 0 top
CAP14476  22u/6.3V_6  [C0603]  123.39 54.92 90 top
CAP14477  22u/6.3V_6  [C0603]  121.45 40.97 180 top
CAP14478  22u/6.3V_6  [C0603]  134.59 35.97 90 bottom
CAP14479  22u/6.3V_6  [C0603]  124.35 61.65 180 top
CAP14480  22u/6.3V_6  [C0603]  131.41 28.23 270 bottom
CAP14481  1U/6.3V_4  [C0402]  114.61 56.59 0 top
CAP14482  1U/6.3V_4  [C0402]  112.07 55.96 180 top
CAP14483  1U/6.3V_4  [C0402]  115.58 59.11 0 top
CAP14490  0.1U/16V_4  [C0402]  34.84 17.69 0 top
CAP14491  0.1U/16V_4  [C0402]  29.56 20.1 270 top
CAP14493  10u/10V_4  [C0402_2]  102.46 84.34 0 bottom
CCP4019  1U/6.3V_4  [C0402]  174.21 20.23 90 top
CCP4089  0.1U/16V_4  [C0402]  95.09 17.53 180 bottom
CCP4090  *0.1U/16V_4  [C0402]  78.19 15.76 270 bottom
CCP4092  2200P/50V_4  [C0402]  39.39 20.3 90 bottom
CCP4093  2200P/50V_4  [C0402]  98.77 37.12 90 bottom
CCP4094  *2200P/50V_4  [C0402]  82.24 19.6 270 bottom
CCP4156  0.1U/16V_4  [C0402]  20.03 56.17 90 bottom
CCP4157  0.1U/16V_4  [C0402]  21.18 56.17 90 bottom
CCP4166  0.22u/10V_4  [C0402]  17.85 63.46 180 bottom
CCP4167  0.22u/10V_4  [C0402]  17.85 62.31 180 bottom
CCP4168  0.22u/10V_4  [C0402]  18.61 65.11 90 bottom
CCP4169  0.22u/10V_4  [C0402]  17.59 65.13 90 bottom
CCP4195  0.1U/16V_4  [C0402]  20.41 27.21 90 bottom
CCP4196  0.1U/16V_4  [C0402]  21.43 27.21 90 bottom
CCP4197  220U/6.3V_3528  [C3528]  18.7 35.34 270 bottom
CCP4198  470p/50V_4  [C0402]  16.22 34.7 90 bottom
CCP4215  0.1U/16V_4  [C0402]  174.21 26.83 90 top
CCP4216  *0.1U/16V_4  [C0402]  26.76 20.35 180 bottom
CN2  51619-0300N-001  [51619-0300N-001-30P-L]  229.35 21.7 270 bottom
CN3  51653-0080N-001  [51653-0080N-001-8P-L]  175.75 18.85 180 bottom
CN4  50271-0040N-V01  [50271-0040N-V01-4P-L]  185.75 61.6 180 bottom
CN8  NASE0-S6701-TSH4  [NGFF-NASE0-S6701-TSH4-KE-SMT]  192.65 20.2 270 bottom
CN12  59058-01902-001  [HDMI-59058-0190D-001-19P-SMT]  3.25 48 90 bottom
CN17  *AXK750147G  [AXK750147G-50P-LDV]  102.33 13.62 180 bottom
CPM3428  0.1U/16V_4  [C0402]  91.66 42.83 0 bottom
CPM3432  0.1U/16V_4  [C0402]  83.41 49.44 90 bottom
CPM3433  0.1U/16V_4  [C0402]  83.02 37.75 90 top
CPM3434  0.1U/16V_4  [C0402]  74.13 40.55 90 bottom
CPM3435  0.1U/16V_4  [C0402]  85.18 38.26 180 top
CPM3436  1U/6.3V_4  [C0402]  79.47 48.93 0 bottom
CPM3437  1000p/50V_4  [C0402]  75.15 40.55 90 bottom
CPM3438  0.1U/16V_4  [C0402]  75.15 36.61 270 bottom
CPM3439  1U/6.3V_4  [C0402]  84.17 32.93 270 bottom
CPM3440  0.1U/16V_4  [C0402]  78.07 42.32 0 top
CPM3479  0.1U/16V_4  [C0402]  95.85 29.12 90 top
CPM4189  100K_2  [R0201]  25.62 27.21 90 bottom
CPM4192  100K_2  [R0201]  30.45 29.88 90 top
CPM4346  1U/6.3V_4  [C0402]  31.72 34.07 180 top
CPM4429  *0.22u/10V_4  [C0402]  105.5 38.13 0 bottom
CPM4431  0.1U/16V_4  [C0402]  92.93 89.06 270 top
CR5  RB500V-40  [DSM]  75.15 62.14 180 top
CR6  RB500V-40  [DSM]  93.06 29.12 180 top
CR7  RB500V-40  [DSM]  75.15 60.23 180 top
CR8  RB500V-40  [DSM]  93.06 27.21 180 top
CR9  RB500V-40  [DSM]  74.9 31.28 180 bottom
CR15  RB500V-40  [DSM]  103.98 19.97 90 bottom
CR16  *RB500V-40  [DSM]  43.02 62.64 0 top
CRCP4008  ESD_TPD4E05U06DQAR  [SON10-2_5X1-5-0_55H]  143.98 22.51 0 top
CRCP4009  ESD_TPD4E05U06DQAR  [SON10-2_5X1-5-0_55H]  138.52 22.51 0 top
CRCP4010  ESD_TPD4E05U06DQAR  [SON10-2_5X1-5-0_55H]  135.09 22.51 0 top
CRCP4011  ESD_TPD4E05U06DQAR  [SON10-2_5X1-5-0_55H]  131.79 22.51 0 top
CRCP4014  ESD_TPD4E05U06DQAR  [SON10-2_5X1-5-0_55H]  128.49 22.51 0 top
CRCP4028  PDZ5.6B  [DSM]  21.43 34.7 90 bottom
CRCP4042  ESD_TPD4E05U06DQAR  [SON10-2_5X1-5-0_55H]  174.97 24.16 180 bottom
CRCP4043  ESD_TPD4E05U06DQAR  [SON10-2_5X1-5-0_55H]  125.06 22.51 0 top
CRPM3518  RB500V-40  [DSM]  74.26 48.8 180 bottom
CRPM3519  RB500V-40  [DSM]  74.01 46.9 180 bottom
CSM1017  0.047u/16V_4  [C0402]  151.95 81.36 90 top
CSM1018  10u/6.3V_4  [C0402_2]  160.88 86.01 90 bottom
CSM1019  0.047u/16V_4  [C0402]  152.36 87.91 180 top
CSM1020  10u/6.3V_4  [C0402_2]  153.49 80.3 180 top
CSM1021  1U/6.3V_2  [C0201]  156.21 85.92 180 top
CSM1022  1U/6.3V_2  [C0201]  144.24 86.65 90 bottom
CSM1023  10u/6.3V_4  [C0402_2]  150.73 83.85 270 top
CSM1024  1U/6.3V_2  [C0201]  148.09 88.01 90 top
CSM1025  10u/6.3V_4  [C0402_2]  151.3 90.25 180 top
CSM1026  1U/6.3V_2  [C0201]  155.34 89.54 90 top
CSM1027  0.1u/10V_2  [C0201]  156.13 83.65 180 top
CSM1028  1U/6.3V_2  [C0201]  151.04 85.95 0 top
CSM1029  0.1u/10V_2  [C0201]  154.85 80.9 270 top
CSM1030  1U/6.3V_2  [C0201]  150.02 80.85 270 top
CSM2029  0.047u/16V_4  [C0402]  168.9 70.14 90 top
CSM2030  10u/6.3V_4  [C0402_2]  160.18 75.82 270 bottom
CSM2031  10u/6.3V_4  [C0402_2]  173.37 82.7 270 bottom
CSM2032  0.047u/16V_4  [C0402]  168.28 77.73 270 top
CSM2033  10u/6.3V_4  [C0402_2]  170.8 79.69 0 top
CSM2034  1U/6.3V_2  [C0201]  167.18 69.23 0 top
CSM2035  1U/6.3V_2  [C0201]  172.31 82.71 270 bottom
CSM2036  10u/6.3V_4  [C0402_2]  167.73 73.65 0 top
CSM2037  1U/6.3V_2  [C0201]  164.82 74.68 0 top
CSM2038  10u/6.3V_4  [C0402_2]  172.12 74.2 90 top
CSM2039  1U/6.3V_2  [C0201]  165.74 76.86 270 top
CSM2040  0.1u/10V_2  [C0201]  168.97 71.5 180 top
CSM2041  1U/6.3V_2  [C0201]  168.31 76.38 270 top
CSM2042  0.1u/10V_2  [C0201]  171.92 68.3 180 top
CSM2043  1U/6.3V_2  [C0201]  165.06 69.45 90 top
CSM2097  0.047u/16V_4  [C0402]  130.06 84.97 270 top
CSM2098  10u/6.3V_4  [C0402_2]  120.87 90.58 90 bottom
CSM2099  10u/6.3V_4  [C0402_2]  138.47 90.38 180 bottom
CSM2100  0.047u/16V_4  [C0402]  129.38 89.95 90 top
CSM2101  10u/6.3V_4  [C0402_2]  134.02 86.95 0 top
CSM2102  1U/6.3V_2  [C0201]  127.06 86.9 0 top
CSM2103  1U/6.3V_2  [C0201]  138.4 91.47 180 bottom
CSM2104  10u/6.3V_4  [C0402_2]  128.48 88.01 0 top
CSM2105  1U/6.3V_2  [C0201]  125.56 90.15 90 top
CSM2106  10u/6.3V_4  [C0402_2]  125.7 83.19 270 top
CSM2107  1U/6.3V_2  [C0201]  133.44 82.51 180 top
CSM2108  0.1u/10V_2  [C0201]  133.04 88.07 0 top
CSM2109  1U/6.3V_2  [C0201]  131.43 82.73 90 top
CSM2110  0.1u/10V_2  [C0201]  125.74 88.07 0 top
CSM2111  1U/6.3V_2  [C0201]  127.06 82.48 0 top
CSM2129  0.047u/16V_4  [C0402]  111.36 84.97 270 top
CSM2130  10u/6.3V_4  [C0402_2]  104.95 89.57 270 top
CSM2131  0.047u/16V_4  [C0402]  110.71 89.95 90 top
CSM2133  1U/6.3V_2  [C0201]  110.07 86.01 0 top
CSM2134  1U/6.3V_2  [C0201]  119.22 90.08 270 bottom
CSM2135  10u/6.3V_4  [C0402_2]  113.53 87.97 0 top
CSM2136  1U/6.3V_2  [C0201]  115.02 82.48 0 top
CSM2137  10u/6.3V_4  [C0402_2]  108.17 87.54 270 top
CSM2138  1U/6.3V_2  [C0201]  114.95 88.05 180 top
CSM2139  0.1u/10V_2  [C0201]  105.12 86.49 0 top
CSM2140  1U/6.3V_2  [C0201]  105.59 83.39 90 top
CSM2141  0.1u/10V_2  [C0201]  115.87 87.82 270 top
CSM2142  1U/6.3V_2  [C0201]  115.28 86.57 90 top
CSM2156  0.1U/16V_4  [C0402]  60.8 44.43 180 top
CSM2157  4.7uF/10V_4  [C0402_2]  49.8 46.13 270 bottom
CSM2158  0.1U/16V_4  [C0402]  50.89 46.13 270 bottom
CSM2159  4.7uF/10V_4  [C0402_2]  62.37 57.06 90 bottom
CSM2160  0.1U/16V_4  [C0402]  61.28 57.03 90 bottom
CSM3132  10u/6.3V_4  [C0402_2]  108.72 83.35 180 top
D3  RB500V-40  [DSM]  74.01 44.99 0 bottom
D4  *AZ5725-01F.R7G  [ESD-1X0_6-2P]  178.4 82.2 0 top
D21  *AZ5725-01F.R7G  [ESD-1X0_6-2P]  19.8 51.54 270 bottom
D41  RB500V-40  [DSM]  16.93 45.6 180 bottom
D46  AZ5725-01F.R7G  [ESD-1X0_6-2P]  16.73 9.3 90 top
D47  AZ5725-01F.R7G  [ESD-1X0_6-2P]  16.6 15.02 270 top
D48  AZ5725-01F.R7G  [ESD-1X0_6-2P]  17.11 11.54 90 top
D49  AZ5725-01F.R7G  [ESD-1X0_6-2P]  16.86 7.27 90 top
D50  AZ5725-01F.R7G  [ESD-1X0_6-2P]  15.71 19.08 270 top
D51  AZ5725-01F.R7G  [ESD-1X0_6-2P]  73.12 43.49 180 bottom
D60  *AZ1045-04F.R7G  [UDFN10-2_5X1-5-9P]  13.38 42.93 90 top
D61  *AZ1045-04F.R7G  [UDFN10-2_5X1-5-9P]  13.38 47 90 top
EC1  D24V0L1B2LPS-7B  [D-1X0_6-D24V0L1B2LPS]  8.22 67.85 90 top
EC2  0.1u/25V_4  [C0402]  171.29 26.96 270 top
EC3  0.1u/25V_4  [C0402]  171.29 26.96 270 bottom
EU1B2  SN1408009RTER  [QFN16-3X3-5-17P-TPS2546RTER]  205.11 15.95 270 top
EUCP4040  SN1408009RTER  [QFN16-3X3-5-17P-TPS2546RTER]  28.76 30.89 270 bottom
EUPM3247  MEC1322  [QFN132-11X11-5-133P]  82.71 41.04 180 bottom
F2B1  KMC3S200RY  [R0805]  207.61 19.46 270 top
F100  KMC3S150RY  [R0805]  42.84 55.61 270 bottom
F104  CFS06V3T5R0  [R0805]  24.1 33.82 180 bottom
FB1  PBY160808T-600Y-N(60,3A)  [R0603]  70.07 41.18 180 bottom
FB1C2  PBY160808T-600Y-N(60,3A)  [R0603]  20.92 23.15 180 top
FB1C8  PBY160808T-600Y-N(60,3A)  [R0603]  23.84 23.78 90 top
FB1C10  PBY160808T-600Y-N(60,3A)  [R0603]  25.37 23.78 90 top
FB1C11  *PBY160808T-600Y-N(60,3A)  [R0603]  16.98 23.91 270 top
FB1D1  PBY160808T-600Y-N(60,3A)  [R0603]  29.18 15.91 270 top
FB1D2  PBY160808T-600Y-N(60,3A)  [R0603]  32.99 25.94 180 top
HOLE1  *H-C197D197N  [H-C197D197N]  190.75 70.55 0 top
HOLE2  *H-ZHD-1  [H-ZHD-1]  81.75 10.5 0 bottom
HOLE4  *hg-zhd-3  [HG-ZHD-3]  10.75 3.2 0 top
HOLE7  *H-TC197IC182D142PT  [H-TC197IC182D142PT]  154.25 66.09 0 top
HOLE9  *H-TC220IC186D146PT  [H-TC220IC186D146PT]  97.25 66.09 0 top
HOLE18  MBZHD001010  [H-TIC221BC236D142P2]  221.05 20.2 180 bottom
HOLE19  *H-TC220IC186D146PT  [H-TC220IC186D146PT]  154.25 46.09 0 top
HOLE34  *HG-C299D98P2  [HG-C299D98P2]  161.75 95.1 0 top
HOLE35  *HG-C299D158P2  [HG-C299D158P2]  161.75 11.7 0 top
HOLE36  *HG-C299D98P2  [HG-C299D98P2]  212.75 35.2 0 top
HOLE41  *H-C98D98N  [H-C98D98N]  167.75 95.1 0 top
HOLE42  *H-TC220IC186D146PT  [H-TC220IC186D146PT]  97.25 46.09 0 top
HOLE43  *H-ZHD-2  [H-ZHD-2]  11.73 88.91 0 top
HOLE44  *HG-C236D98P2  [HG-C236D98P2]  10.95 59.2 0 top
HOLE45  *spad-re315x1043np  [SPAD-RE315X1043NP]  232.75 19.95 0 top
J1C1  2SJ3080-108111F  [AUDIO-2SJ3080-108111F-6P]  4.67 13.5 90 bottom
J1P2  50271-0040N-V01  [50271-0040N-V01-4P-L]  34.25 14.4 90 bottom
J2  53065-00902-001  [USB-53065-00902-001-9P-SMT]  5.75 28.5 90 bottom
J8L1  51693-04001-V01  [196522-40041-3-40P-LDH]  46.15 66.35 0 bottom
JCP4038  DX07B024XJ1AR1000  [UB31-DX07B024XJ1AR1000-24P-SMT]  6.6 66 90 bottom
JCP4056  51646-0300N-V01  [51646-0300N-V01-30P-L]  133.5 20 180 bottom
JP948  *SHORT_4  [S0402]  217.39 28.99 0 top
JP949  *SHORT_6  [S0603]  83.99 59.98 0 top
JP950  *SHORT_6  [S0603]  43.27 48.04 0 top
JP951  *SHORT_4  [S0402]  55.29 70.67 0 top
JP952  *SHORT_4  [S0402]  102.33 94.9 0 bottom
JP955  *SHORT_6  [S0603]  24 52.28 180 top
JP3507  *SHORT_4  [S0402]  24.35 58.45 0 top
JP3535  *SHORT_6  [S0603]  60.08 71.95 270 bottom
JP3536  *SHORT_6  [S0603]  63.72 96.15 0 bottom
JP3537  *SHORT_6  [S0603]  74.46 86.51 0 top
JP3538  *SHORT_6  [S0603]  79.52 79.34 270 top
JP3539  *SHORT_6  [S0603]  172.27 33.86 180 bottom
JP3545  *SHORT_6  [S0603]  166.47 28.56 180 bottom
JP3546  *0_5%_6  [R0603]  180.77 37.07 90 bottom
JP3547  *SHORT_6  [S0603]  174.49 37.54 90 bottom
JP3571  *SHORT_4  [S0402]  63.34 85.76 90 bottom
JP5076  *0_5%_6  [R0603]  50.13 50.83 180 top
JP5100  *0_5%_4  [R0402]  98.39 86.27 0 bottom
L10  DLP11SA900HL2L/90ohm/0.15A  [CHOKE-DLP11SN900HL2L-4P-1]  17.14 62.75 270 top
L11  DLP11SA900HL2L/90ohm/0.15A  [CHOKE-DLP11SN900HL2L-4P-1]  15.41 62.77 270 top
L12  DLP11SA900HL2L/90ohm/0.15A  [CHOKE-DLP11SN900HL2L-4P-1]  13.68 69.76 0 top
L13  DLP11SA900HL2L/90ohm/0.15A  [CHOKE-DLP11SN900HL2L-4P-1]  13.68 71.28 0 top
L15  2.2uH/0.12A_6  [R0603]  105.63 33.54 0 bottom
L16  DLW21SN900HQ2L/280mA/90ohm  [CHOKE-DLW21S-4P]  16.4 41.92 180 top
L17  DLW21SN900HQ2L/280mA/90ohm  [CHOKE-DLW21S-4P]  16.4 43.82 180 top
L18  DLW21SN900HQ2L/280mA/90ohm  [CHOKE-DLW21S-4P]  16.4 45.98 180 top
L19  DLW21SN900HQ2L/280mA/90ohm  [CHOKE-DLW21S-4P]  16.4 48.01 180 top
LCP4022  MCM2012B900GBE/400mA/90ohm  [FILTER-MCM2012B900GBE-4P]  16.22 68.11 180 top
LCP4041  MCM2012B900GBE/400mA/90ohm  [FILTER-MCM2012B900GBE-4P]  23.97 30.89 180 bottom
LCP4042  DLP11SA900HL2L/90ohm/0.15A  [CHOKE-DLP11SN900HL2L-4P-1]  20.92 29.37 90 bottom
LED1  12-12/S2BHC-A30/2C  [LED12-22-S2ST3D-C30-2C-3P-SMT]  4.3 88.2 270 bottom
LED2  12-12/S2BHC-A30/2C  [LED12-22-S2ST3D-C30-2C-3P-SMT]  4.3 80.2 270 bottom
MR1  APX8132AI-TRG  [SOT23_213-3_3-2]  174.75 87.6 270 top
NOREF  -  []  107.23 12.44 0 top
NOREF#2  -  [unnamed#2]  190.11 93.71 0 top
NOREF#3  -  []  73.5 -62.58 0 top
NOREF#4  -  [unnamed#2]  18.1 3.18 0 top
NOREF#5  -  []  185.01 83.47 0 top
NOREF#6  -  [unnamed#2]  226.66 10.4 0 top
NOREF#7  -  []  22.7 -103.22 0 top
NOREF#8  -  [unnamed#2]  58.03 42.48 90 bottom
NOREF#9  -  [unnamed#2]  17.95 3.31 180 bottom
NOREF#10  -  []  89.68 10.45 180 bottom
NOREF#11  -  [unnamed#2]  65.62 75.08 0 bottom
NOREF#12  -  [unnamed#2]  66.53 47.6 0 bottom
NOREF#13  -  []  186.02 84.62 180 bottom
NOREF#14  -  [unnamed#2]  69.73 82.54 270 bottom
NOREF#15  -  [unnamed#2]  74.82 80.55 180 bottom
NOREF#16  -  [unnamed#2]  190.31 93.76 180 bottom
NOREF#17  -  [unnamed#2]  233.39 10.12 180 bottom
NOREF#18  -  [unnamed#2]  59.47 54.18 270 bottom
PC1  1U/6.3V_4  [C0402]  54.78 68.56 0 top
PC2  0.1u/25V_4  [C0402]  191.09 41.99 270 bottom
PC3  0.1U/16V_4  [C0402]  64.74 85.38 0 top
PC4  220u/2V_7343H1.0  [CC7343]  131.28 34.7 90 bottom
PC5  220u/2V_7343H1.0  [CC7343]  139.31 32.06 270 bottom
PC6  *220u/2V_7343H1.0  [CC7343]  177.33 59.22 90 bottom
PC7  *220u/2V_7343H1.0  [CC7343]  193.91 51.18 0 bottom
PC8  *47P/50V_4  [C0402]  66.77 20.73 90 top
PC9  *47P/50V_4  [C0402]  67.91 20.73 90 top
PC10  220u/2V_7343H1.0  [CC7343]  165.7 48.93 270 bottom
PC11  220u/2V_7343H1.0  [CC7343]  160.88 48.93 270 bottom
PC12  *1000p/50V_4  [C0402]  158.05 31.25 270 top
PC14  1000p/50V_4  [C0402]  179.35 44.39 270 top
PC15  *1000p/50V_4  [C0402]  185.67 42.56 270 top
PC16  *4.7uF/10V_4  [C0402_2]  186.08 38.81 270 top
PC17  *0.1u/25V_4  [C0402]  188.09 41.51 90 top
PC18  4.7uF/10V_4  [C0402_2]  179.41 38.01 90 bottom
PC19  *0.1u/25V_4  [C0402]  179.16 42.55 90 top
PC20  4.7uF/10V_4  [C0402_2]  172.51 38.08 180 bottom
PC21  *0.1u/25V_4  [C0402]  168.55 39.19 180 top
PC22  1000p/50V_4  [C0402]  166.55 36.68 270 top
PC23  0.01U/50V_4  [C0402]  194.62 41.69 0 top
PC24  33n/25V_4  [C0402]  201.85 32.09 90 top
PC25  2200P/50V_4  [C0402]  200.83 32.28 90 bottom
PC26  0.01U/50V_4  [C0402]  190.15 33.39 180 top
PC27  *1000p/50V_4  [C0402]  40.53 22.49 0 bottom
PC46  0.1U/16V_4  [C0402]  185.77 73.64 180 bottom
PC301  1u/25V_4  [C0402]  205.58 25.81 270 top
PC302  1u/25V_4  [C0402]  210.15 25.94 270 top
PC303  10u/6.3V_6  [C0603]  205.71 30.39 0 top
PC304  0.1U/16V_4  [C0402]  206.09 29.12 0 top
PC305  0.1U/16V_4  [C0402]  210.15 27.85 90 top
PC306  10u/6.3V_6  [C0603]  211.42 27.85 90 top
PC307  0.1U/16V_4  [C0402]  207.61 23.27 90 top
PC308  *0.1U/16V_4  [C0402]  206.6 23.27 90 top
PC309  1000p/50V_4  [C0402]  207.87 30.13 90 top
PC310  1000p/50V_4  [C0402]  208.88 30.13 90 top
PC1051  100p/50V_4  [C0402]  52.28 25.15 180 top
PC1142  10u/25V_8  [C0805]  36.8 27.34 180 bottom
PC1143  10u/25V_8  [C0805]  36.8 29.62 180 bottom
PC1144  *1u/6.3V_4  [C0402]  46.45 49.69 180 top
PC1146  1U/6.3V_4  [C0402]  79.85 61.98 90 top
PC1147  1U/6.3V_4  [C0402]  97.99 94.04 180 bottom
PC1148  1U/6.3V_4  [C0402]  26.13 57.44 0 top
PC1149  1U/6.3V_4  [C0402]  42.16 51.47 270 top
PC1150  1U/6.3V_4  [C0402]  102.86 85.81 270 bottom
PC1151  *10u/25V_8  [C0805]  181.02 40.07 270 bottom
PC1152  *10u/25V_8  [C0805]  182.99 40.07 270 bottom
PC1153  22u/25V_8  [C0805]  39.72 32.42 90 bottom
PC1154  22u/25V_8  [C0805]  40.35 29.62 0 bottom
PC1155  22u/25V_8  [C0805]  38.4 25.36 0 bottom
PC1156  22u/25V_8  [C0805]  41.18 25.54 90 bottom
PC1157  22u/25V_8  [C0805]  44.3 29.76 180 bottom
PC1158  22u/25V_8  [C0805]  44.29 27.77 180 bottom
PC1159  22u/25V_8  [C0805]  63.62 66.11 270 bottom
PC1160  22u/25V_8  [C0805]  54.72 18.83 90 bottom
PC1161  22u/25V_8  [C0805]  40.91 19.44 270 bottom
PC1162  22u/25V_8  [C0805]  43.15 19.39 270 bottom
PC1163  22u/25V_8  [C0805]  167.25 30.9 270 bottom
PC1164  22u/25V_8  [C0805]  175.12 31.66 90 bottom
PC1165  22u/25V_8  [C0805]  179.88 31.67 90 bottom
PC1166  22u/25V_8  [C0805]  177.6 31.66 90 bottom
PC1167  22u/25V_8  [C0805]  55.42 26.28 0 bottom
PC1168  22u/25V_8  [C0805]  63.21 24.06 180 bottom
PC1169  10u/25V_8  [C0805]  63.85 69.64 90 bottom
PC1170  10u/25V_8  [C0805]  63.72 93.17 0 bottom
PC1171  10u/25V_8  [C0805]  63.72 91.19 0 bottom
PC1172  10u/25V_8  [C0805]  81.54 76.67 270 bottom
PC1173  10u/25V_8  [C0805]  83.51 76.67 270 bottom
PC1174  10u/25V_8  [C0805]  74.77 89.29 0 bottom
PC1175  10u/25V_8  [C0805]  77.44 88.46 270 bottom
PC1176  10u/25V_8  [C0805]  169.86 32.15 0 bottom
PC1177  10u/25V_8  [C0805]  169.32 34.13 0 bottom
PC1178  10u/25V_8  [C0805]  164.13 30.36 270 bottom
PC1179  10u/25V_8  [C0805]  162.15 30.36 270 bottom
PC1180  10u/25V_8  [C0805]  171.12 41.71 0 bottom
PC1181  10u/25V_8  [C0805]  173.81 42.86 270 bottom
PC1182  10u/25V_8  [C0805]  61.83 69.64 90 bottom
PC1183  *0.22U/25V_6  [C0603]  184.22 37.07 90 bottom
PC1184  0.22u/25V_6  [C0603]  175.95 37.83 90 bottom
PC1185  0.22u/25V_6  [C0603]  198.51 36.82 90 bottom
PC1186  0.22u/25V_6  [C0603]  172.83 35.33 180 bottom
PC1187  0.22u/25V_6  [C0603]  162.83 28.18 180 top
PC1188  1u/25V_4  [C0402]  63.47 23.64 180 top
PC1189  1u/25V_4  [C0402]  47.61 27.11 180 top
PC1190  1u/25V_4  [C0402]  67.43 67.11 0 top
PC1191  1u/25V_4  [C0402]  67.4 68.11 0 top
PC1192  22u/6.3V_6  [C0603]  38.45 67.09 270 top
PC1193  22u/6.3V_6  [C0603]  36.92 67.09 270 top
PC1194  22u/6.3V_6  [C0603]  35.4 67.09 90 top
PC1195  22u/6.3V_6  [C0603]  33.88 67.09 90 top
PC1196  10u/25V_6  [C0603]  28.54 70.01 270 top
PC1197  10u/25V_6  [C0603]  30.07 70.01 270 top
PC1198  22u/6.3V_6  [C0603]  125.21 26.87 270 bottom
PC1199  22u/6.3V_6  [C0603]  135.99 26.87 270 bottom
PC1200  22u/6.3V_6  [C0603]  121.77 29.64 180 bottom
PC1201  22u/6.3V_6  [C0603]  121.73 31.1 180 bottom
PC1202  22u/6.3V_6  [C0603]  118.79 37.55 180 bottom
PC1203  22u/6.3V_6  [C0603]  120.67 34.55 270 bottom
PC1204  22u/6.3V_6  [C0603]  58.39 80.01 180 top
PC1205  22u/6.3V_6  [C0603]  53.54 86.19 270 bottom
PC1206  22u/6.3V_6  [C0603]  58.43 83.06 180 top
PC1207  22u/6.3V_6  [C0603]  81.5 65.3 90 bottom
PC1208  22u/6.3V_6  [C0603]  80.08 65.3 90 bottom
PC1209  22u/6.3V_6  [C0603]  72.68 68.57 0 top
PC1210  22u/6.3V_6  [C0603]  78.4 70.67 270 bottom
PC1211  22u/6.3V_6  [C0603]  80.17 70.67 270 bottom
PC1212  22u/6.3V_6  [C0603]  81.77 70.34 270 bottom
PC1213  22u/6.3V_6  [C0603]  75.86 69.84 270 top
PC1214  22u/6.3V_6  [C0603]  83.2 70.34 270 bottom
PC1215  22u/6.3V_6  [C0603]  83.05 65.3 90 bottom
PC1216  22u/6.3V_6  [C0603]  77.28 69.71 270 top
PC1217  22u/6.3V_6  [C0603]  78.58 65.3 90 bottom
PC1218  22u/6.3V_6  [C0603]  72.68 67.14 0 top
PC1219  22u/6.3V_6  [C0603]  163 74.4 180 top
PC1220  22u/6.3V_6  [C0603]  111.84 81.92 0 top
PC1221  22u/6.3V_6  [C0603]  110.19 87.86 0 top
PC1222  22u/6.3V_6  [C0603]  79.41 95.51 270 bottom
PC1223  22u/6.3V_6  [C0603]  154.03 85.7 180 top
PC1224  22u/6.3V_6  [C0603]  57.9 86.19 90 bottom
PC1225  22u/6.3V_6  [C0603]  59.31 86.19 90 bottom
PC1226  22u/6.3V_6  [C0603]  54.65 89.56 270 top
PC1227  22u/6.3V_6  [C0603]  56.08 89.56 270 top
PC1228  22u/6.3V_6  [C0603]  57.5 89.57 270 top
PC1229  22u/6.3V_6  [C0603]  56.44 86.19 90 bottom
PC1230  22u/6.3V_6  [C0603]  54.97 86.19 90 bottom
PC1231  22u/6.3V_6  [C0603]  61.77 89.57 270 top
PC1232  22u/6.3V_6  [C0603]  86.63 85.65 180 top
PC1233  22u/6.3V_6  [C0603]  39.43 69.32 0 top
PC1234  22u/6.3V_6  [C0603]  39.38 70.82 0 top
PC1235  22u/6.3V_6  [C0603]  79.16 89.08 270 top
PC1236  22u/6.3V_6  [C0603]  80.86 89.08 270 top
PC1237  22u/6.3V_6  [C0603]  82.58 89.08 270 top
PC1238  22u/6.3V_6  [C0603]  79.16 89.08 270 bottom
